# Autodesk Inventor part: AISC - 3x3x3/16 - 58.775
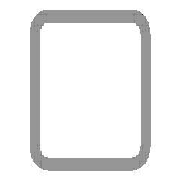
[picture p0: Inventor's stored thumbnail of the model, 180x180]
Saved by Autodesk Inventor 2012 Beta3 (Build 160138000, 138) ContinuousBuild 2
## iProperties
IsCustomPart: 1
_CCFamilyMember: 9
_CCFamilyDisplayName: ANSI AISC (Square) - Tube
_FrameMemberDoc: Frame Member File
_Version: 15.0.0
_GetPNFromCC: 1
Created: 2011-01
Part Number: AISC - 3x3x3/16 - 58.775
Material: Steel, Mild
Description: Tube
Document SubType Name: Modeling
Standard: ANSI
Designer: Beta-8540w
Standards Organization: ANSI
Language: en-US
Size Designation: 3x3x3/16
Categories: <MemberInstance><Categories><Category DisplayName="Structural Shapes" InternalName="089c4875-fa83-4c05-b084-43b9cc11f5ed" Mnemonic="GRDR"><CategoryParameter Dis
Stock Number: 3x3x3/16
Density: 7.86 g/cm^3
G_L: 58.775 in
G_W: 3.000 in
G_H: 3.000 in
+AE3CA65D-4403-45DE-BD14-7280831DFD21+CUTDETAIL1: Cut
Author: Beta-8540w
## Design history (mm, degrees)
node "Start plane"
node "End plane"
sketch "Sketch"
  geometry: L1 (-38.1, -28.575)-(-38.1, 28.575); L2 (-28.575, 38.1)-(28.575, 38.1); L3 (38.1, 28.575)-(38.1, -28.575); L4 (28.575, -38.1)-(-28.575, -38.1); L5 (-28.575, 33.337)-(28.575, 33.338); L6 (33.338, 28.575)-(33.338, -28.575); L7 (28.575, -33.337)-(-28.575, -33.338); L8 (-33.338, -28.575)-(-33.338, 28.575); L9 (0, 56.102)-(0, -56.102) reference; L10 (-56.102, 0)-(56.102, 0) reference; A1 r 9.525 centre (-28.575, -28.575) between (-38.1, -28.575) and (-28.575, -38.1); A2 r 9.525 centre (-28.575, 28.575) between (-28.575, 38.1) and (-38.1, 28.575); A3 r 9.525 centre (28.575, 28.575) between (38.1, 28.575) and (28.575, 38.1); A4 r 9.525 centre (28.575, -28.575) between (28.575, -38.1) and (38.1, -28.575); A5 r 4.763 centre (-28.575, 28.575) between (-28.575, 33.337) and (-33.338, 28.575); A6 r 4.763 centre (28.575, 28.575) between (33.338, 28.575) and (28.575, 33.338); A7 r 4.763 centre (28.575, -28.575) between (28.575, -33.337) and (33.338, -28.575); A8 r 4.763 centre (-28.575, -28.575) between (-33.338, -28.575) and (-28.575, -33.338)
  constraints: 16 end point, 16 point on circle, 8 centre point, 8 tangent, 4 parallel, 3 equal radius, 2 perpendicular, 7 other
  dimensions: "d10" = 76.2 distance between parallel lines of L2 L4 (= G_H); "d11" = 76.2 distance between parallel lines of L1 L3 (= G_W); "d12" = 4.7625 distance between parallel lines of L3 L6 (= G_T); "d15" = 38.1 distance between parallel lines of L2 L10 (= 0.5 x d10); "d16" = 38.1 distance between parallel lines of L9 L3 (= 0.5 x d11); "d17" = 9.525 radius of A1 (= G_IR)
extrude "Body" new body sketch "Sketch" stored distance "d3" = 1492.89148 (= G_L); taper "d4" = 0 deg
node "Driven Length"
  sketch "Sketch3"
    geometry: L1 (0, 0)-(10, 0) reference
    constraints: 2 end point, 1 horizontal
  workplane "Work Plane3"
  sketch "Sketch4"
    geometry: L1 (-2, 0)-(12, 0) reference; L2 (-2, 1492.891)-(12, 1492.891) reference
    dimensions: "d19" = 1492.89148 distance between parallel lines of L1 L2 (derived)
workplane "Work Plane4"
split "Split1"
body "Solid1"
other parameters: "G_W" = 76.2 [user parameter; used in 1 equation term], "G_H" = 76.2 [user parameter; used in 1 equation term], "G_T" = 4.7625 [user parameter; used in 1 equation term], "G_IR" = 9.525 [user parameter; used in 1 equation term], "G_L" = 1492.89148 (= d19) [user parameter; used in 1 equation term], "G_OFFSET_START" = 0 [user parameter; used in 1 equation term], "G_OFFSET_END" = -31.10852 [user parameter; used in 1 equation term], "d13" = 0 (computed from G_OFFSET_START), "d14" = 1492.89148 (= G_OFFSET_END + B_L), "B_L" = 1524 [user parameter; used in 1 equation term], "d18" = 90 deg
